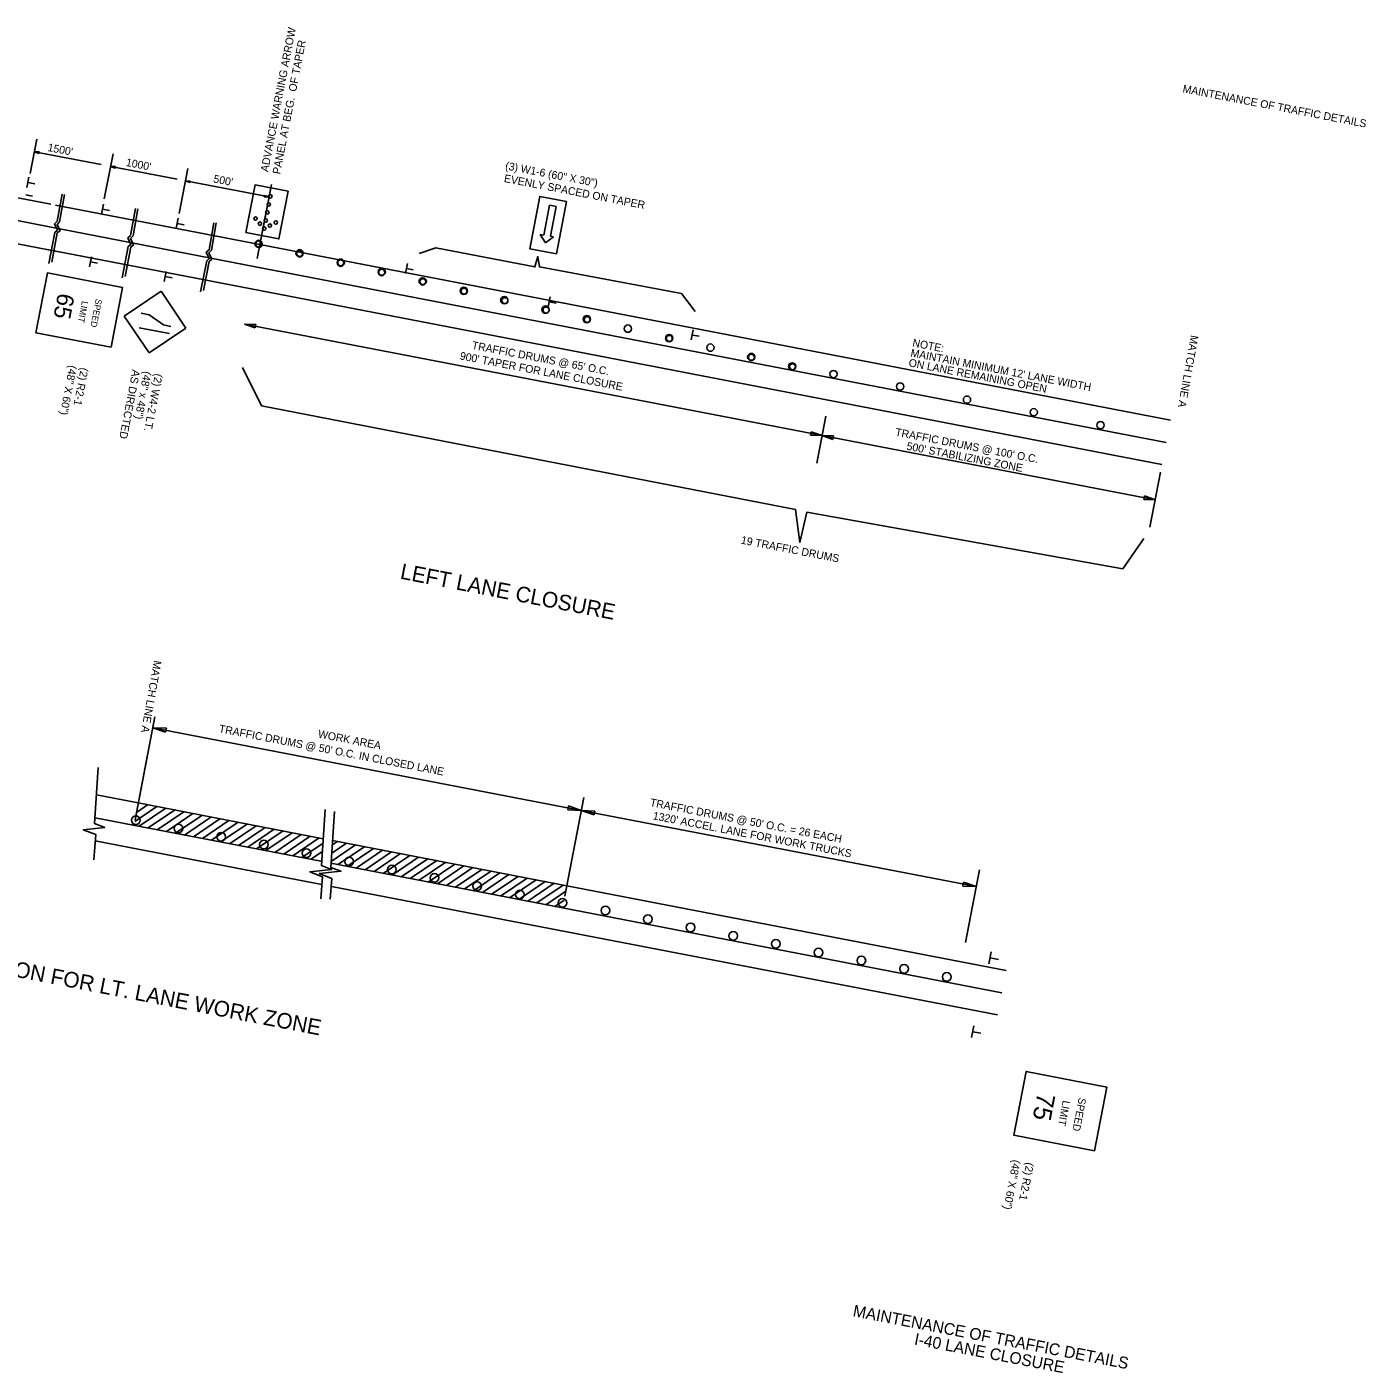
# Model space of a CAD drawing. Extents: x 606975 to 609391, y 416008 to 419482.
# Drawn here: x 607026.1 to 607129, y 419378.5 to 419482 of the extents above; entities that cross this region are included whole.
import ezdxf

# ---------------------------------------------------------------- set-up
doc = ezdxf.new("R2010")
doc.units = 0
doc.layers.add('Default', color=7, linetype='Continuous')
doc.layers.add('G-ANNO-TEXT', color=7, linetype='Continuous')

msp = doc.modelspace()

# ---------------------------------------------------------------- linework, layer by layer
at = {"layer": 'Default'}
for p, q in [((607026.89, 419473.38), (607026.38, 419470.74)), ((607026.71, 419472.42), (607031.83, 419471.43)), ((607027.06, 419472.29), (607026.71, 419472.42)), ((607027.08, 419472.4), (607026.71, 419472.42)), ((607027.06, 419472.3), (607026.77, 419472.41)), ((607027.08, 419472.39), (607026.77, 419472.41)), ((607027.08, 419472.38), (607026.83, 419472.39)), ((607027.07, 419472.31), (607026.83, 419472.39)), ((607027.07, 419472.32), (607026.89, 419472.38)), ((607027.08, 419472.37), (607026.89, 419472.38)), ((607027.08, 419472.36), (607026.95, 419472.37)), ((607027.07, 419472.33), (607026.95, 419472.37)), ((607027.08, 419472.35), (607027.02, 419472.36)), ((607027.07, 419472.34), (607027.02, 419472.36)), ((607027.06, 419472.29), (607027.08, 419472.4)), ((607032.75, 419472.25), (607032.08, 419468.79)), ((607032.57, 419471.29), (607037.69, 419470.3)), ((607032.92, 419471.16), (607032.57, 419471.29)), ((607032.95, 419471.27), (607032.57, 419471.29)), ((607032.93, 419471.17), (607032.63, 419471.27)), ((607032.94, 419471.26), (607032.63, 419471.27)), ((607032.94, 419471.25), (607032.69, 419471.26)), ((607032.93, 419471.18), (607032.69, 419471.26)), ((607032.93, 419471.19), (607032.75, 419471.25)), ((607032.94, 419471.24), (607032.75, 419471.25)), ((607032.94, 419471.23), (607032.81, 419471.24)), ((607032.93, 419471.2), (607032.81, 419471.24)), ((607032.94, 419471.22), (607032.88, 419471.23)), ((607032.93, 419471.21), (607032.88, 419471.23)), ((607032.92, 419471.16), (607032.95, 419471.27)), ((607038.5, 419471.14), (607037.83, 419467.68)), ((607026.14, 419469.68), (607026.29, 419470.45)), ((607026.23, 419470.06), (607026.75, 419469.96)), ((607038.31, 419470.18), (607044.74, 419468.94)), ((607038.67, 419470.05), (607038.31, 419470.18)), ((607038.69, 419470.16), (607038.31, 419470.18)), ((607038.67, 419470.06), (607038.37, 419470.16)), ((607038.69, 419470.15), (607038.37, 419470.16)), ((607038.69, 419470.14), (607038.44, 419470.15)), ((607038.67, 419470.07), (607038.44, 419470.15)), ((607038.67, 419470.08), (607038.5, 419470.14)), ((607038.69, 419470.13), (607038.5, 419470.14)), ((607038.68, 419470.12), (607038.56, 419470.13)), ((607038.68, 419470.09), (607038.56, 419470.13)), ((607038.68, 419470.11), (607038.62, 419470.12)), ((607038.68, 419470.1), (607038.62, 419470.12)), ((607038.67, 419470.05), (607038.69, 419470.16)), ((607019.83, 419469.96), (607027.98, 419468.39)), ((607026.04, 419469.11), (607026.57, 419469.01)), ((607044.93, 419469.9), (607044.26, 419466.44)), ((607044.38, 419469.06), (607044.36, 419468.95)), ((607044.37, 419469.02), (607044.43, 419469)), ((607044.38, 419469.06), (607044.74, 419468.94)), ((607044.38, 419469.05), (607044.68, 419468.95)), ((607044.38, 419469.04), (607044.62, 419468.96)), ((607044.38, 419469.03), (607044.55, 419468.97)), ((607044.38, 419469.02), (607044.49, 419468.98)), ((607019.5, 419468.26), (607028, 419466.62)), ((607028.33, 419468.31), (607044.03, 419465.28)), ((607031.86, 419467.62), (607032.01, 419468.38)), ((607031.94, 419468), (607032.47, 419467.9)), ((607044.36, 419468.97), (607044.62, 419468.96)), ((607044.36, 419468.96), (607044.68, 419468.95)), ((607044.36, 419468.95), (607044.74, 419468.94)), ((607044.37, 419469), (607044.43, 419469)), ((607044.37, 419468.99), (607044.49, 419468.98)), ((607044.37, 419468.98), (607044.55, 419468.97)), ((607066.29, 419468.3), (607065.85, 419466.01)), ((607066.29, 419468.3), (607066.8, 419468.2)), ((607066.8, 419468.2), (607066.36, 419465.92)), ((607037.61, 419466.53), (607037.76, 419467.3)), ((607044.49, 419467.66), (607043.83, 419464.2)), ((607019.17, 419466.55), (607028.58, 419464.73)), ((607028, 419466.62), (607043.71, 419463.58)), ((607037.69, 419466.91), (607038.22, 419466.81)), ((607065.85, 419466.01), (607065.59, 419466.06)), ((607065.59, 419466.06), (607066, 419465.41)), ((607066.36, 419465.92), (607066.61, 419465.87)), ((607027.68, 419464.91), (607043.38, 419461.88)), ((607044.04, 419465.29), (607114.02, 419451.78)), ((607066, 419465.41), (607066.61, 419465.87)), ((607030.95, 419463.57), (607031.1, 419464.33)), ((607031.03, 419463.95), (607031.56, 419463.85)), ((607036.69, 419462.44), (607036.84, 419463.21)), ((607036.77, 419462.82), (607037.3, 419462.72)), ((607043.71, 419463.58), (607113.69, 419450.07)), ((607055.37, 419463.83), (607055.22, 419463.06)), ((607055.3, 419463.44), (607055.83, 419463.34)), ((607043.38, 419461.88), (607113.36, 419448.37)), ((607036.44, 419461.69), (607033.61, 419459.78)), ((607036.44, 419461.69), (607038.34, 419458.86)), ((607066.35, 419461.27), (607066.2, 419460.5)), ((607066.29, 419460.89), (607066.81, 419460.79)), ((607033.61, 419459.78), (607035.52, 419456.95)), ((607034.92, 419460), (607035.52, 419459.88)), ((607035.52, 419459.88), (607036.62, 419459.1)), ((607034.76, 419458.89), (607037.09, 419458.44)), ((607038.34, 419458.86), (607035.52, 419456.95)), ((607036.62, 419459.1), (607037.19, 419458.99)), ((607087.24, 419450.61), (607042.86, 419459.17)), ((607042.86, 419459.17), (607043.73, 419459.14)), ((607043.68, 419458.88), (607042.86, 419459.17)), ((607043.73, 419459.14), (607043.68, 419458.88)), ((607077.34, 419458.72), (607077.19, 419457.95)), ((607077.28, 419458.33), (607077.8, 419458.23)), ((607087.52, 419452.08), (607086.83, 419448.49)), ((607086.36, 419450.64), (607086.41, 419450.9)), ((607087.24, 419450.61), (607086.36, 419450.64)), ((607086.41, 419450.9), (607087.24, 419450.61)), ((607112.84, 419445.66), (607087.24, 419450.61)), ((607087.24, 419450.61), (607088.12, 419450.57)), ((607088.07, 419450.31), (607087.24, 419450.61)), ((607088.12, 419450.57), (607088.07, 419450.31)), ((607113.25, 419447.78), (607112.43, 419443.55)), ((607111.96, 419445.7), (607112.01, 419445.96)), ((607112.84, 419445.66), (607111.96, 419445.7)), ((607112.01, 419445.96), (607112.84, 419445.66)), ((607035.97, 419428.98), (607034.44, 419421.06)), ((607068.74, 419421.79), (607035.81, 419428.14)), ((607035.81, 419428.14), (607036.85, 419428.1)), ((607036.79, 419427.8), (607035.81, 419428.14)), ((607036.85, 419428.1), (607036.79, 419427.8)), ((607035.41, 419426.07), (607034.44, 419421.06)), ((607035.41, 419426.07), (607034.44, 419421.06)), ((607035.41, 419426.07), (607034.44, 419421.06)), ((607031.48, 419422.98), (607034.69, 419422.36)), ((607068.93, 419422.78), (607067.47, 419415.2)), ((607034.42, 419420.94), (607036.11, 419422.08)), ((607034.56, 419421.64), (607035.41, 419422.22)), ((607034.69, 419422.36), (607048.91, 419419.61)), ((607034.77, 419420.57), (607036.8, 419421.95)), ((607035.46, 419420.44), (607037.56, 419421.86)), ((607036.15, 419420.3), (607038.19, 419421.68)), ((607036.85, 419420.17), (607038.88, 419421.55)), ((607037.54, 419420.04), (607039.58, 419421.41)), ((607067.7, 419421.83), (607067.76, 419422.13)), ((607068.74, 419421.79), (607067.7, 419421.83)), ((607067.76, 419422.13), (607068.74, 419421.79)), ((607099.09, 419415.93), (607068.74, 419421.79)), ((607068.74, 419421.79), (607069.78, 419421.74)), ((607069.72, 419421.44), (607068.74, 419421.79)), ((607069.78, 419421.74), (607069.72, 419421.44)), ((607031.37, 419421.23), (607034.3, 419420.66)), ((607034.3, 419420.66), (607048.72, 419417.88)), ((607038.24, 419419.9), (607040.27, 419421.28)), ((607038.93, 419419.77), (607040.97, 419421.15)), ((607039.63, 419419.63), (607041.66, 419421.01)), ((607040.32, 419419.5), (607042.36, 419420.88)), ((607041.01, 419419.37), (607043.05, 419420.74)), ((607041.71, 419419.23), (607043.74, 419420.61)), ((607042.4, 419419.1), (607044.44, 419420.48)), ((607031.39, 419419.45), (607034.01, 419418.95)), ((607043.1, 419418.96), (607045.13, 419420.34)), ((607043.79, 419418.83), (607045.83, 419420.21)), ((607044.49, 419418.7), (607046.52, 419420.07)), ((607045.18, 419418.56), (607047.22, 419419.94)), ((607045.87, 419418.43), (607047.91, 419419.81)), ((607046.57, 419418.29), (607048.6, 419419.67)), ((607049.61, 419419.14), (607049.99, 419419.4)), ((607049.62, 419419.48), (607067.62, 419416)), ((607034.01, 419418.95), (607048.8, 419416.09)), ((607047.26, 419418.16), (607048.89, 419419.26)), ((607047.96, 419418.03), (607048.84, 419418.63)), ((607049.52, 419417.87), (607051.38, 419419.14)), ((607049.56, 419418.51), (607050.69, 419419.27)), ((607050.04, 419417.62), (607052.08, 419419)), ((607050.73, 419417.49), (607052.77, 419418.87)), ((607051.43, 419417.36), (607053.46, 419418.73)), ((607052.12, 419417.22), (607054.16, 419418.6)), ((607052.82, 419417.09), (607054.85, 419418.47)), ((607053.51, 419416.95), (607055.55, 419418.33)), ((607049.5, 419417.73), (607067.29, 419414.29)), ((607054.21, 419416.82), (607056.24, 419418.2)), ((607054.9, 419416.69), (607056.94, 419418.06)), ((607055.59, 419416.55), (607057.63, 419417.93)), ((607056.29, 419416.42), (607058.32, 419417.8)), ((607056.98, 419416.28), (607059.02, 419417.66)), ((607057.68, 419416.15), (607059.71, 419417.53)), ((607058.37, 419416.02), (607060.41, 419417.39)), ((607059.07, 419415.88), (607061.1, 419417.26)), ((607059.76, 419415.75), (607061.8, 419417.13)), ((607060.45, 419415.61), (607062.49, 419416.99)), ((607061.15, 419415.48), (607063.18, 419416.86)), ((607061.84, 419415.35), (607063.88, 419416.72)), ((607062.54, 419415.21), (607064.57, 419416.59)), ((607063.23, 419415.08), (607065.27, 419416.46)), ((607063.93, 419414.94), (607065.96, 419416.32)), ((607098.05, 419415.97), (607098.11, 419416.28)), ((607098.11, 419416.28), (607099.09, 419415.93)), ((607099.34, 419417.22), (607098.26, 419411.64)), ((607049.55, 419415.95), (607066.96, 419412.59)), ((607064.62, 419414.81), (607066.66, 419416.19)), ((607065.31, 419414.68), (607067.35, 419416.05)), ((607066.01, 419414.54), (607067.54, 419415.58)), ((607067.62, 419416), (607101.39, 419409.48)), ((607099.09, 419415.93), (607098.05, 419415.97)), ((607066.7, 419414.41), (607067.41, 419414.88)), ((607067.29, 419414.29), (607101.06, 419407.78)), ((607066.96, 419412.59), (607100.73, 419406.07)), ((607100.07, 419410), (607100.25, 419410.91)), ((607100.17, 419410.45), (607100.79, 419410.33)), ((607098.73, 419404.33), (607098.91, 419405.24)), ((607098.83, 419404.78), (607099.45, 419404.66))]:
    msp.add_line(p, q, dxfattribs=at)
for points in [[(607028.83, 419469.15), (607028.46, 419467.08), (607028.25, 419466.87), (607028.48, 419466.39), (607028.28, 419466.22), (607027.82, 419463.82)], [(607029.02, 419469.13), (607028.65, 419467.03), (607028.45, 419466.83), (607028.68, 419466.34), (607028.47, 419466.18), (607028.04, 419463.92)], [(607034.47, 419468.06), (607034.1, 419465.99), (607033.89, 419465.79), (607034.12, 419465.3), (607033.92, 419465.14), (607033.46, 419462.73)], [(607034.67, 419468.04), (607034.29, 419465.95), (607034.09, 419465.74), (607034.32, 419465.25), (607034.12, 419465.09), (607033.68, 419462.83)], [(607040.49, 419466.96), (607040.13, 419464.89), (607039.92, 419464.69), (607040.15, 419464.2), (607039.95, 419464.04), (607039.48, 419461.64)], [(607040.69, 419466.94), (607040.32, 419464.85), (607040.11, 419464.64), (607040.34, 419464.16), (607040.14, 419463.99), (607039.71, 419461.74)], [(607056.28, 419464.59), (607057.55, 419465.04), (607065.17, 419463.57), (607065.39, 419464.36), (607065.52, 419463.57), (607076.43, 419461.53), (607077.48, 419460.15)], [(607042.71, 419455.83), (607044.15, 419452.89), (607085.21, 419444.91), (607085.54, 419442.39), (607086.06, 419444.71), (607110.35, 419440.37), (607111.96, 419442.7)], [(607031.62, 419425.08), (607031.34, 419420.78), (607032.12, 419420.48), (607030.46, 419420.31), (607031.42, 419419.93), (607031.28, 419418)], [(607049.05, 419421.85), (607048.76, 419417.55), (607049.55, 419417.25), (607047.88, 419417.08), (607048.84, 419416.69), (607048.72, 419415)], [(607049.76, 419421.71), (607049.48, 419417.41), (607050.26, 419417.11), (607048.6, 419416.94), (607049.56, 419416.55), (607049.45, 419414.97)]]:
    msp.add_lwpolyline(points, dxfattribs=at)
for points in [[(607042.97, 419466.21), (607043.67, 419469.87), (607046.2, 419469.38), (607045.5, 419465.72)], [(607064.78, 419464.96), (607065.55, 419468.98), (607067.6, 419468.58), (607066.83, 419464.57)], [(607032.61, 419457.39), (607026.83, 419458.51), (607027.71, 419463.1), (607033.49, 419461.98)], [(607108.17, 419395.63), (607101.98, 419396.82), (607102.93, 419401.73), (607109.12, 419400.53)]]:
    msp.add_lwpolyline(points, close=True, dxfattribs=at)
for centre, radius in [((607044.84, 419468.99), 0.131), ((607044.72, 419468.37), 0.131), ((607043.71, 419467.28), 0.131), ((607044.04, 419466.89), 0.131), ((607044.49, 419467.13), 0.131), ((607044.61, 419467.75), 0.131), ((607045.26, 419466.98), 0.131), ((607044.37, 419466.51), 0.131), ((607044.81, 419466.74), 0.131), ((607043.94, 419465.33), 0.281), ((607043.92, 419465.33), 0.229), ((607043.93, 419465.33), 0.229), ((607047.09, 419464.61), 0.281), ((607047.09, 419464.6), 0.229), ((607050.25, 419463.89), 0.281), ((607050.25, 419463.88), 0.229), ((607053.4, 419463.17), 0.281), ((607053.4, 419463.15), 0.229), ((607056.55, 419462.45), 0.281), ((607056.56, 419462.43), 0.229), ((607059.71, 419461.73), 0.281), ((607059.72, 419461.7), 0.229), ((607062.82, 419461.01), 0.281), ((607062.87, 419460.97), 0.229), ((607065.99, 419460.28), 0.281), ((607066.03, 419460.25), 0.229), ((607069.16, 419459.55), 0.281), ((607069.19, 419459.52), 0.229), ((607072.32, 419458.82), 0.281), ((607075.49, 419458.09), 0.281), ((607075.5, 419458.07), 0.229), ((607078.66, 419457.36), 0.281), ((607081.8, 419456.64), 0.281), ((607081.81, 419456.62), 0.229), ((607084.95, 419455.92), 0.281), ((607084.97, 419455.89), 0.229), ((607088.12, 419455.33), 0.281), ((607093.24, 419454.37), 0.281), ((607098.38, 419453.36), 0.281), ((607103.51, 419452.39), 0.281), ((607108.64, 419451.4), 0.281), ((607034.5, 419421.03), 0.333), ((607037.78, 419420.4), 0.333), ((607041.06, 419419.77), 0.333), ((607044.34, 419419.16), 0.333), ((607047.62, 419418.5), 0.333), ((607050.9, 419417.86), 0.333), ((607054.18, 419417.24), 0.333), ((607057.46, 419416.61), 0.333), ((607060.74, 419415.97), 0.333), ((607064.02, 419415.32), 0.333), ((607067.3, 419414.68), 0.333), ((607070.59, 419414.09), 0.333), ((607073.86, 419413.43), 0.333), ((607077.14, 419412.8), 0.333), ((607080.42, 419412.15), 0.333), ((607083.7, 419411.53), 0.333), ((607086.97, 419410.86), 0.333), ((607090.26, 419410.25), 0.333), ((607093.54, 419409.61), 0.333), ((607096.82, 419408.99), 0.333)]:
    msp.add_circle(centre, radius, dxfattribs=at)

# ---------------------------------------------------------------- texts
for s, height, rotation, p in [('ADVANCE WARNING ARROW', 0.6, 79.0745, (607044.67, 419470.83)), ('PANEL AT BEG.  OF TAPER', 0.6, 79.0745, (607045.59, 419470.65)), ("1500'", 0.6, 349.0745, (607027.69, 419472.48)), ("1000'", 0.6, 349.0745, (607033.71, 419471.33)), ('(3) W1-6 (60" X 30")', 0.6, 349.0821, (607062.86, 419471.07)), ("500'", 0.6, 349.0745, (607040.43, 419470.06)), ('EVENLY SPACED ON TAPER', 0.6, 349.0821, (607062.76, 419470.1)), ('65', 1.304, 259.0745, (607028.53, 419461.61)), ('LIMIT', 0.487, 259.0745, (607030.37, 419460.97)), ('SPEED', 0.487, 259.0745, (607031.43, 419461.14)), ("TRAFFIC DRUMS @ 65' O.C.", 0.6, 349.0745, (607060.29, 419457.27)), ('NOTE:', 0.6, 349.0745, (607094.15, 419457.46)), ('MATCH LINE A', 0.6, 259.8804, (607115.58, 419458.35)), ("900' TAPER FOR LANE CLOSURE", 0.6, 349.0745, (607059.37, 419456.46)), ("MAINTAIN MINIMUM 12' LANE WIDTH", 0.6, 349.0745, (607094.01, 419456.69)), ('(48" X 60")', 0.6, 259.0745, (607029.39, 419456.04)), ('(2) R2-1', 0.6, 259.0745, (607030.28, 419455.86)), ('AS DIRECTED ', 0.6, 259.0745, (607034.25, 419455.7)), ('ON LANE REMAINING OPEN', 0.6, 349.0745, (607093.86, 419455.93)), ('(48" x 48")', 0.6, 259.0745, (607035.12, 419455.58)), ('(2) W4-2 LT.', 0.6, 259.0745, (607035.98, 419455.4)), ("TRAFFIC DRUMS @ 100' O.C.", 0.6, 349.0745, (607092.83, 419450.6)), ("500' STABILIZING ZONE", 0.6, 349.0745, (607093.7, 419449.52)), ('19 TRAFFIC DRUMS', 0.6, 349.0745, (607080.97, 419442.3)), ('LEFT LANE CLOSURE', 1.2, 349.0745, (607054.76, 419439.61)), ('MATCH LINE A', 0.6, 259.8804, (607035.89, 419433.35)), ("TRAFFIC DRUMS @ 50' O.C. IN CLOSED LANE", 0.6, 349.0745, (607040.85, 419427.8)), ('WORK AREA', 0.6, 349.0745, (607048.47, 419427.4)), ("TRAFFIC DRUMS @ 50' O.C. = 26 EACH", 0.6, 349.0745, (607073.98, 419422.13)), ("1320' ACCEL. LANE FOR WORK TRUCKS", 0.6, 349.0745, (607074.2, 419421.11)), ('DIVERSION FOR LT. LANE WORK ZONE', 1.2, 349.0745, (607018.77, 419410.25)), ('75', 1.396, 259.0745, (607103.81, 419400.14)), ('SPEED', 0.573, 259.0745, (607106.98, 419399.74)), ('LIMIT', 0.573, 259.0745, (607105.75, 419399.53)), ('(48" X 60")', 0.6, 259.0745, (607101.91, 419394.97)), ('(2) R2-1', 0.6, 259.0745, (607102.94, 419394.77))]:
    msp.add_text(s, height=height, rotation=rotation, dxfattribs=at).set_placement(p)
at = {"layer": 'G-ANNO-TEXT'}
for s, height, p in [('MAINTENANCE OF TRAFFIC DETAILS', 0.6, (607114.92, 419476.99)), ('MAINTENANCE OF TRAFFIC DETAILS', 0.9, (607089.56, 419382.92)), ('I-40 LANE CLOSURE', 0.9, (607094.28, 419380.75))]:
    msp.add_text(s, height=height, rotation=349.0745, dxfattribs=at).set_placement(p)

doc.saveas('drawing.dxf')
